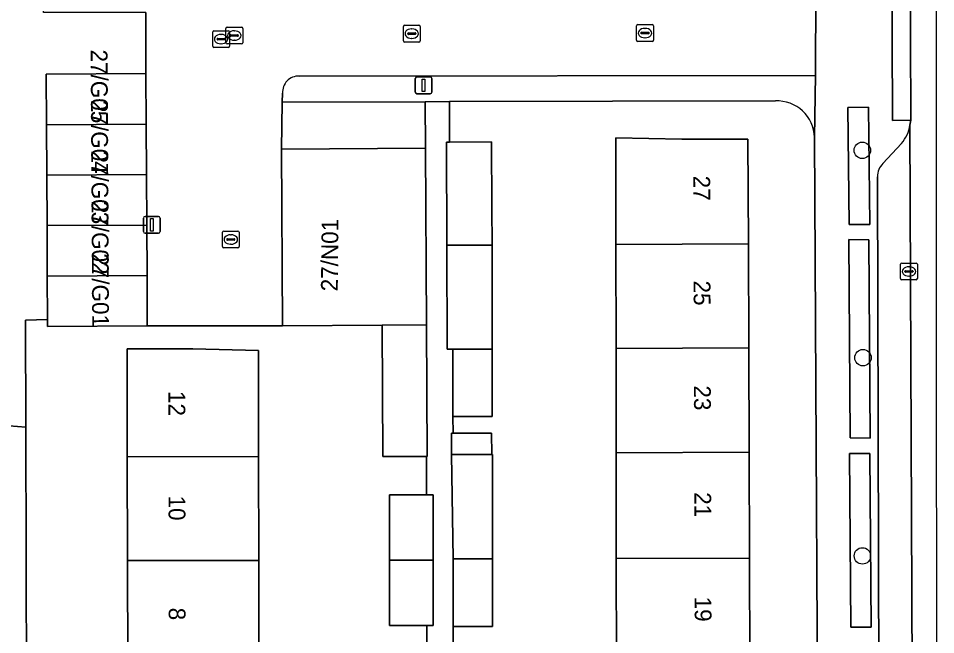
# Model space of a CAD drawing. Extents: x 160732 to 162107, y 387428 to 388479.
# Drawn here: x 161247.8 to 161302.4, y 387899 to 387935.7 of the extents above; entities that cross this region are included whole.
import ezdxf

# ---------------------------------------------------------------- set-up
doc = ezdxf.new("R2010")
doc.units = 0
for name, color, linetype in [('IMGEO_Boom', 7, 'Continuous'), ('IMGEO_Erf', 7, 'Continuous'), ('IMGEO_Groenvoorziening', 7, 'Continuous'), ('IMGEO_Haag', 7, 'Continuous'), ('IMGEO_Kolk', 7, 'Continuous'), ('IMGEO_Lichtmast', 7, 'Continuous'), ('IMGEO_Pand', 7, 'Continuous'), ('IMGEO_Pand_nummerreeks', 7, 'Continuous'), ('IMGEO_Parkeervlak_open', 7, 'Continuous'), ('IMGEO_Rijbaan_lokaal_gesloten', 7, 'Continuous'), ('IMGEO_Rijbaan_lokaal_open', 7, 'Continuous'), ('IMGEO_Rioolput', 7, 'Continuous'), ('IMGEO_Voetpad_open', 7, 'Continuous')]:
    doc.layers.add(name, color=color, linetype=linetype)

msp = doc.modelspace()

# ---------------------------------------------------------------- linework, layer by layer
at = {"layer": 'IMGEO_Boom'}
for centre in [(161298.046, 387927.814), (161298.085, 387915.474), (161298.054, 387903.682)]:
    msp.add_circle(centre, 0.489, dxfattribs=at)
at = {"layer": 'IMGEO_Erf'}
for points in [[(161292.882, 387930.752), (161273.477, 387930.71), (161273.482, 387928.303), (161275.982, 387928.317), (161276.004, 387924.389), (161276.016, 387922.172), (161276.021, 387919.765), (161276.021, 387915.984), (161276.021, 387911.974), (161273.683, 387911.974), (161273.684, 387910.985), (161275.979, 387910.992), (161275.994, 387909.712), (161276.036, 387909.712), (161276.036, 387907.273), (161276.036, 387903.515), (161276.036, 387899.482), (161273.698, 387899.482), (161273.712, 387894.91)], [(161283.411, 387897.345), (161283.404, 387903.526), (161283.396, 387909.817), (161283.389, 387916.018), (161283.382, 387922.214), (161283.375, 387928.562), (161287.301, 387928.476), (161291.227, 387928.476), (161291.281, 387922.255), (161291.3, 387916.054), (161291.32, 387909.852), (161291.34, 387903.538), (161291.359, 387897.354)], [(161295.457, 387880.84), (161295.205, 387928.599)], [(161269.924, 387891.076), (161269.919, 387894.963), (161272.127, 387894.966), (161272.122, 387899.541), (161269.91, 387899.538), (161269.905, 387903.424), (161269.9, 387907.312), (161272.113, 387907.315), (161272.11, 387909.603), (161269.512, 387909.6), (161269.469, 387917.409), (161263.537, 387917.376), (161255.49, 387917.362), (161249.554, 387917.329), (161249.552, 387917.745), (161248.248, 387917.717), (161248.263, 387911.338), (161248.335, 387880.236)], [(161250.168, 387878.512), (161254.356, 387878.531), (161254.344, 387884.882), (161254.333, 387891.056), (161254.322, 387897.231), (161254.31, 387903.406), (161254.299, 387909.58), (161254.287, 387916), (161258.196, 387916), (161262.105, 387915.903), (161262.115, 387909.59), (161262.124, 387903.415), (161262.134, 387897.241), (161262.143, 387891.066), (161262.152, 387884.891), (161262.162, 387878.605), (161269.546, 387878.658), (161269.489, 387882.632), (161272.021, 387882.669), (161272.016, 387887.191), (161269.929, 387887.189), (161269.924, 387891.076)]]:
    msp.add_lwpolyline(points, dxfattribs=at)
msp.add_arc((161292.972, 387928.519), 2.235, 2.045, 92.3052, dxfattribs=at)
at = {"layer": 'IMGEO_Groenvoorziening'}
for points in [[(161272.028, 387930.707), (161263.523, 387930.688), (161263.479, 387927.886), (161272.043, 387927.933)], [(161298.502, 387923.406), (161298.417, 387930.379), (161297.188, 387930.364), (161297.273, 387923.391)], [(161298.442, 387922.488), (161297.235, 387922.509), (161297.327, 387910.71), (161298.51, 387910.69)], [(161298.569, 387899.442), (161298.492, 387909.784), (161297.277, 387909.775), (161297.354, 387899.433)]]:
    msp.add_lwpolyline(points, close=True, dxfattribs=at)
at = {"layer": 'IMGEO_Haag'}
for points in [[(161298.502, 387923.406), (161298.417, 387930.379), (161297.188, 387930.364), (161297.273, 387923.391)], [(161298.442, 387922.488), (161297.235, 387922.509), (161297.327, 387910.71), (161298.51, 387910.69)], [(161298.569, 387899.442), (161298.492, 387909.784), (161297.277, 387909.775), (161297.354, 387899.433)]]:
    msp.add_lwpolyline(points, close=True, dxfattribs=at)
at = {"layer": 'IMGEO_Kolk'}
for p, q in [((161270.729, 387934.33), (161270.729, 387935.182)), ((161270.804, 387935.256), (161271.656, 387935.256)), ((161271.73, 387935.182), (161271.73, 387934.33)), ((161284.612, 387934.365), (161284.612, 387935.217)), ((161284.687, 387935.291), (161285.539, 387935.291)), ((161285.613, 387935.217), (161285.613, 387934.365)), ((161260.166, 387934.217), (161260.166, 387935.069)), ((161260.241, 387935.143), (161261.093, 387935.143)), ((161260.425, 387934.637), (161260.425, 387934.649)), ((161260.468, 387934.686), (161260.866, 387934.686)), ((161260.654, 387934.923), (161260.679, 387934.923)), ((161260.909, 387934.649), (161260.909, 387934.637)), ((161261.167, 387935.069), (161261.167, 387934.217)), ((161270.988, 387934.75), (161270.988, 387934.762)), ((161271.426, 387934.713), (161271.028, 387934.713)), ((161271.031, 387934.799), (161271.429, 387934.799)), ((161271.217, 387935.036), (161271.242, 387935.036)), ((161271.472, 387934.762), (161271.472, 387934.75)), ((161284.871, 387934.785), (161284.871, 387934.797)), ((161285.309, 387934.748), (161284.911, 387934.748)), ((161284.914, 387934.834), (161285.312, 387934.834)), ((161285.1, 387935.071), (161285.125, 387935.071)), ((161285.355, 387934.797), (161285.355, 387934.785)), ((161261.093, 387934.143), (161260.241, 387934.143)), ((161260.863, 387934.6), (161260.465, 387934.6)), ((161260.677, 387934.363), (161260.652, 387934.363)), ((161271.656, 387934.256), (161270.804, 387934.256)), ((161271.24, 387934.476), (161271.215, 387934.476)), ((161285.539, 387934.291), (161284.687, 387934.291)), ((161285.123, 387934.511), (161285.098, 387934.511)), ((161259.959, 387922.084), (161259.959, 387922.936)), ((161260.034, 387923.01), (161260.886, 387923.01)), ((161260.447, 387922.79), (161260.472, 387922.79)), ((161260.96, 387922.936), (161260.96, 387922.084)), ((161260.218, 387922.504), (161260.218, 387922.516)), ((161260.656, 387922.467), (161260.258, 387922.467)), ((161260.261, 387922.553), (161260.659, 387922.553)), ((161260.47, 387922.23), (161260.445, 387922.23)), ((161260.702, 387922.516), (161260.702, 387922.504)), ((161260.886, 387922.01), (161260.034, 387922.01)), ((161300.322, 387920.182), (161300.322, 387921.034)), ((161300.397, 387921.108), (161301.249, 387921.108)), ((161301.323, 387921.034), (161301.323, 387920.182)), ((161300.581, 387920.602), (161300.581, 387920.614)), ((161301.019, 387920.565), (161300.621, 387920.565)), ((161300.624, 387920.651), (161301.022, 387920.651)), ((161300.81, 387920.888), (161300.835, 387920.888)), ((161301.065, 387920.614), (161301.065, 387920.602)), ((161301.249, 387920.108), (161300.397, 387920.108)), ((161300.833, 387920.328), (161300.808, 387920.328))]:
    msp.add_line(p, q, dxfattribs=at)
for points in [[(161270.729, 387934.33), (161270.729, 387935.182)], [(161270.804, 387935.256), (161271.656, 387935.256)], [(161271.73, 387935.182), (161271.73, 387934.33)], [(161284.612, 387934.365), (161284.612, 387935.217)], [(161284.687, 387935.291), (161285.539, 387935.291)], [(161285.613, 387935.217), (161285.613, 387934.365)], [(161260.166, 387934.217), (161260.166, 387935.069)], [(161260.241, 387935.143), (161261.093, 387935.143)], [(161261.167, 387935.069), (161261.167, 387934.217)], [(161261.093, 387934.143), (161260.241, 387934.143)], [(161271.656, 387934.256), (161270.804, 387934.256)], [(161285.539, 387934.291), (161284.687, 387934.291)], [(161259.959, 387922.084), (161259.959, 387922.936)], [(161260.034, 387923.01), (161260.886, 387923.01)], [(161260.96, 387922.936), (161260.96, 387922.084)], [(161260.886, 387922.01), (161260.034, 387922.01)], [(161300.322, 387920.182), (161300.322, 387921.034)], [(161300.397, 387921.108), (161301.249, 387921.108)], [(161301.323, 387921.034), (161301.323, 387920.182)], [(161301.249, 387920.108), (161300.397, 387920.108)]]:
    msp.add_lwpolyline(points, dxfattribs=at)
for centre, radius, start, end in [((161270.806, 387935.18), 0.0765, 91.552, 178.448), ((161270.806, 387935.18), 0.0765, 91.552, 178.448), ((161271.654, 387935.18), 0.0765, 1.552, 88.448), ((161271.654, 387935.18), 0.0765, 1.552, 88.448), ((161284.689, 387935.215), 0.0765, 91.552, 178.448), ((161284.689, 387935.215), 0.0765, 91.552, 178.448), ((161285.537, 387935.215), 0.0765, 1.552, 88.448), ((161285.537, 387935.215), 0.0765, 1.552, 88.448), ((161260.243, 387935.067), 0.0765, 91.552, 178.448), ((161260.243, 387935.067), 0.0765, 91.552, 178.448), ((161260.465, 387934.646), 0.0403, 85.8775, 175.7526), ((161260.462, 387934.636), 0.0366, 178.938, 274.7102), ((161260.866, 387934.643), 0.043, 264.8664, 352.4533), ((161260.87, 387934.648), 0.0386, 1.7309, 96.639), ((161261.091, 387935.067), 0.0765, 1.552, 88.448), ((161261.091, 387935.067), 0.0765, 1.552, 88.448), ((161271.028, 387934.759), 0.0403, 85.8775, 175.7526), ((161271.025, 387934.749), 0.0366, 178.938, 274.7102), ((161271.429, 387934.756), 0.043, 264.8664, 352.4533), ((161271.433, 387934.761), 0.0386, 1.7309, 96.639), ((161284.911, 387934.794), 0.0403, 85.8775, 175.7526), ((161284.908, 387934.784), 0.0366, 178.938, 274.7102), ((161285.312, 387934.791), 0.043, 264.8664, 352.4533), ((161285.316, 387934.796), 0.0386, 1.7309, 96.639), ((161260.243, 387934.219), 0.0765, 181.552, 268.448), ((161260.243, 387934.219), 0.0765, 181.552, 268.448), ((161261.091, 387934.219), 0.0765, 271.552, 358.448), ((161261.091, 387934.219), 0.0765, 271.552, 358.448), ((161270.806, 387934.332), 0.0765, 181.552, 268.448), ((161270.806, 387934.332), 0.0765, 181.552, 268.448), ((161271.654, 387934.332), 0.0765, 271.552, 358.448), ((161271.654, 387934.332), 0.0765, 271.552, 358.448), ((161284.689, 387934.367), 0.0765, 181.552, 268.448), ((161284.689, 387934.367), 0.0765, 181.552, 268.448), ((161285.537, 387934.367), 0.0765, 271.552, 358.448), ((161285.537, 387934.367), 0.0765, 271.552, 358.448), ((161260.036, 387922.934), 0.0765, 91.552, 178.448), ((161260.036, 387922.934), 0.0765, 91.552, 178.448), ((161260.884, 387922.934), 0.0765, 1.552, 88.448), ((161260.884, 387922.934), 0.0765, 1.552, 88.448), ((161260.036, 387922.086), 0.0765, 181.552, 268.448), ((161260.036, 387922.086), 0.0765, 181.552, 268.448), ((161260.258, 387922.513), 0.0403, 85.8775, 175.7526), ((161260.255, 387922.503), 0.0366, 178.938, 274.7102), ((161260.659, 387922.51), 0.043, 264.8664, 352.4533), ((161260.663, 387922.515), 0.0386, 1.7309, 96.639), ((161260.884, 387922.086), 0.0765, 271.552, 358.448), ((161260.884, 387922.086), 0.0765, 271.552, 358.448), ((161300.399, 387921.032), 0.0765, 91.552, 178.448), ((161300.399, 387921.032), 0.0765, 91.552, 178.448), ((161301.247, 387921.032), 0.0765, 1.552, 88.448), ((161301.247, 387921.032), 0.0765, 1.552, 88.448), ((161300.621, 387920.611), 0.0403, 85.8775, 175.7526), ((161300.618, 387920.601), 0.0366, 178.938, 274.7102), ((161301.022, 387920.608), 0.043, 264.8664, 352.4533), ((161301.026, 387920.613), 0.0386, 1.7309, 96.639), ((161300.399, 387920.184), 0.0765, 181.552, 268.448), ((161300.399, 387920.184), 0.0765, 181.552, 268.448), ((161301.247, 387920.184), 0.0765, 271.552, 358.448), ((161301.247, 387920.184), 0.0765, 271.552, 358.448)]:
    msp.add_arc(centre, radius, start, end, dxfattribs=at)
for centre, major_axis, ratio, start_param, end_param in [((161260.653, 387934.643), (-0.387, 0.002), 0.722429, 4.712389, 7.853982), ((161260.678, 387934.643), (-0.39, 0.002), 0.717154, 1.570796, 4.712389), ((161271.216, 387934.756), (-0.387, 0.002), 0.722429, 4.712389, 7.853982), ((161271.241, 387934.756), (-0.39, 0.002), 0.717154, 1.570796, 4.712389), ((161285.099, 387934.791), (-0.387, 0.002), 0.722429, 4.712389, 7.853982), ((161285.124, 387934.791), (-0.39, 0.002), 0.717154, 1.570796, 4.712389), ((161260.446, 387922.51), (-0.387, 0.002), 0.722429, 4.712389, 7.853982), ((161260.471, 387922.51), (-0.39, 0.002), 0.717154, 1.570796, 4.712389), ((161300.809, 387920.608), (-0.387, 0.002), 0.722429, 4.712389, 7.853982), ((161300.834, 387920.608), (-0.39, 0.002), 0.717154, 1.570796, 4.712389)]:
    msp.add_ellipse(centre, major_axis=major_axis, ratio=ratio, start_param=start_param, end_param=end_param, dxfattribs=at)
at = {"layer": 'IMGEO_Lichtmast'}
for p, q in [((161271.437, 387931.279), (161271.437, 387932.079)), ((161271.437, 387932.079), (161271.437, 387931.279)), ((161271.537, 387932.179), (161272.327, 387932.179)), ((161272.327, 387932.179), (161271.537, 387932.179)), ((161272.427, 387932.079), (161272.427, 387931.279)), ((161272.427, 387931.279), (161272.427, 387932.079)), ((161272.327, 387931.179), (161271.537, 387931.179)), ((161271.537, 387931.179), (161272.327, 387931.179)), ((161255.262, 387922.979), (161255.262, 387923.779)), ((161255.262, 387923.779), (161255.262, 387922.979)), ((161255.362, 387923.879), (161256.152, 387923.879)), ((161256.152, 387923.879), (161255.362, 387923.879)), ((161256.252, 387923.779), (161256.252, 387922.979)), ((161256.252, 387922.979), (161256.252, 387923.779)), ((161256.152, 387922.879), (161255.362, 387922.879)), ((161255.362, 387922.879), (161256.152, 387922.879))]:
    msp.add_line(p, q, dxfattribs=at)
for points in [[(161271.857, 387932.054), (161272.007, 387932.054), (161272.007, 387931.304), (161271.857, 387931.304), (161271.857, 387932.054)], [(161255.682, 387923.754), (161255.832, 387923.754), (161255.832, 387923.004), (161255.682, 387923.004), (161255.682, 387923.754)]]:
    msp.add_lwpolyline(points, dxfattribs=at)
for centre, start, end in [((161271.537, 387932.079), 90, 180), ((161271.537, 387932.079), 90, 180), ((161272.327, 387932.079), 0, 90), ((161272.327, 387932.079), 360, 90), ((161271.537, 387931.279), 180, 270), ((161271.537, 387931.279), 180, 270), ((161272.327, 387931.279), 270, 0), ((161272.327, 387931.279), 270, 0), ((161255.362, 387923.779), 90, 180), ((161255.362, 387923.779), 90, 180), ((161256.152, 387923.779), 0, 90), ((161256.152, 387923.779), 360, 90), ((161255.362, 387922.979), 180, 270), ((161255.362, 387922.979), 180, 270), ((161256.152, 387922.979), 270, 0), ((161256.152, 387922.979), 270, 0)]:
    msp.add_arc(centre, 0.1, start, end, dxfattribs=at)
at = {"layer": 'IMGEO_Pand'}
for points in [[(161255.406, 387932.376), (161249.47, 387932.343), (161249.487, 387929.34), (161255.423, 387929.373)], [(161255.423, 387929.373), (161249.487, 387929.34), (161249.504, 387926.337), (161255.44, 387926.37)], [(161273.482, 387928.303), (161273.288, 387928.302), (161273.313, 387922.164), (161273.516, 387922.164), (161273.683, 387922.165), (161276.016, 387922.172), (161276.004, 387924.389), (161275.982, 387928.317)], [(161283.375, 387928.562), (161283.382, 387922.214), (161291.281, 387922.255), (161291.227, 387928.476), (161287.301, 387928.476)], [(161272.043, 387927.933), (161263.479, 387927.886), (161263.537, 387917.376), (161269.469, 387917.409), (161272.101, 387917.423)], [(161255.44, 387926.37), (161249.504, 387926.337), (161249.52, 387923.334), (161255.456, 387923.368)], [(161255.456, 387923.368), (161249.52, 387923.334), (161249.537, 387920.332), (161255.473, 387920.365)], [(161276.021, 387919.765), (161276.016, 387922.172), (161273.683, 387922.165), (161273.516, 387922.164), (161273.313, 387922.164), (161273.339, 387915.973), (161273.551, 387915.973), (161273.683, 387915.974), (161276.021, 387915.984)], [(161283.382, 387922.214), (161283.389, 387916.018), (161291.3, 387916.054), (161291.281, 387922.255)], [(161255.473, 387920.365), (161249.537, 387920.332), (161249.552, 387917.745), (161249.554, 387917.329), (161255.49, 387917.362)], [(161272.101, 387917.423), (161269.469, 387917.409), (161269.512, 387909.6), (161272.11, 387909.603), (161272.144, 387909.603)], [(161291.32, 387909.852), (161291.3, 387916.054), (161283.389, 387916.018), (161283.396, 387909.817)], [(161254.287, 387916), (161254.299, 387909.58), (161262.115, 387909.59), (161262.105, 387915.903), (161258.196, 387916)], [(161273.683, 387911.974), (161276.021, 387911.974), (161276.021, 387915.984), (161273.683, 387915.974)], [(161275.979, 387910.992), (161273.684, 387910.985), (161273.586, 387910.985), (161273.586, 387909.713), (161273.698, 387909.713), (161275.994, 387909.712)], [(161254.31, 387903.406), (161262.124, 387903.415), (161262.115, 387909.59), (161254.299, 387909.58)], [(161276.036, 387907.273), (161276.036, 387909.712), (161275.994, 387909.712), (161273.698, 387909.713), (161273.586, 387909.713), (161273.698, 387903.511), (161276.036, 387903.515)], [(161291.34, 387903.538), (161291.32, 387909.852), (161283.396, 387909.817), (161283.404, 387903.526)], [(161272.495, 387907.315), (161272.113, 387907.315), (161269.9, 387907.312), (161269.905, 387903.424), (161272.5, 387903.427)], [(161273.698, 387899.482), (161276.036, 387899.482), (161276.036, 387903.515), (161273.698, 387903.511)], [(161283.404, 387903.526), (161283.411, 387897.345), (161291.359, 387897.354), (161291.34, 387903.538)], [(161254.322, 387897.231), (161262.134, 387897.241), (161262.124, 387903.415), (161254.31, 387903.406)], [(161272.5, 387903.427), (161269.905, 387903.424), (161269.91, 387899.538), (161272.122, 387899.541), (161272.505, 387899.541)]]:
    msp.add_lwpolyline(points, close=True, dxfattribs=at)
at = {"layer": 'IMGEO_Parkeervlak_open'}
for points in [[(161301.088, 387878.113), (161300.884, 387929.313)], [(161300.386, 387928.226), (161299.273, 387927.025)], [(161298.953, 387926.242), (161299.074, 387881.148)]]:
    msp.add_lwpolyline(points, dxfattribs=at)
for centre, radius, start, end in [((161298.672, 387929.669), 2.241, 319.9102, 350.8608), ((161300.007, 387926.268), 1.054, 134.1128, 181.429)]:
    msp.add_arc(centre, radius, start, end, dxfattribs=at)
at = {"layer": 'IMGEO_Rijbaan_lokaal_gesloten'}
msp.add_lwpolyline([(161300.888, 387939.893), (161300.899, 387939.625), (161300.931, 387929.617), (161300.884, 387929.313), (161301.088, 387878.113), (161301.089, 387875.8), (161302.479, 387875.8), (161302.479, 387897.971), (161302.464, 387915.139), (161302.464, 387992.392), (161300.785, 387992.369), (161300.83, 387991.744), (161300.779, 387991.22)], close=True, dxfattribs=at)
at = {"layer": 'IMGEO_Rijbaan_lokaal_open'}
for points in [[(161264.524, 387932.232), (161295.254, 387932.26), (161295.274, 387937.307), (161271.508, 387937.226)], [(161255.398, 387936.01), (161255.406, 387932.376), (161255.423, 387929.373), (161255.44, 387926.37), (161255.456, 387923.368), (161255.473, 387920.365), (161255.49, 387917.362), (161263.537, 387917.376), (161263.479, 387927.886), (161263.523, 387930.688), (161263.54, 387931.219)]]:
    msp.add_lwpolyline(points, dxfattribs=at)
msp.add_arc((161264.496, 387931.275), 0.958, 88.3174, 183.3465, dxfattribs=at)
at = {"layer": 'IMGEO_Rioolput'}
for p, q in [((161259.38, 387934.006), (161259.38, 387934.858)), ((161259.455, 387934.932), (161260.307, 387934.932)), ((161259.868, 387934.712), (161259.893, 387934.712)), ((161260.381, 387934.858), (161260.381, 387934.006)), ((161259.639, 387934.426), (161259.639, 387934.438)), ((161260.077, 387934.389), (161259.679, 387934.389)), ((161259.682, 387934.475), (161260.08, 387934.475)), ((161259.891, 387934.152), (161259.866, 387934.152)), ((161260.123, 387934.438), (161260.123, 387934.426)), ((161260.307, 387933.932), (161259.455, 387933.932))]:
    msp.add_line(p, q, dxfattribs=at)
for points in [[(161259.38, 387934.006), (161259.38, 387934.858)], [(161259.455, 387934.932), (161260.307, 387934.932)], [(161260.381, 387934.858), (161260.381, 387934.006)], [(161260.307, 387933.932), (161259.455, 387933.932)]]:
    msp.add_lwpolyline(points, dxfattribs=at)
for centre, radius, start, end in [((161259.457, 387934.856), 0.0765, 91.552, 178.448), ((161259.457, 387934.856), 0.0765, 91.552, 178.448), ((161260.305, 387934.856), 0.0765, 1.552, 88.448), ((161260.305, 387934.856), 0.0765, 1.552, 88.448), ((161259.679, 387934.435), 0.0403, 85.8775, 175.7526), ((161259.676, 387934.425), 0.0366, 178.938, 274.7102), ((161260.08, 387934.432), 0.043, 264.8664, 352.4533), ((161260.084, 387934.437), 0.0386, 1.7309, 96.639), ((161259.457, 387934.008), 0.0765, 181.552, 268.448), ((161259.457, 387934.008), 0.0765, 181.552, 268.448), ((161260.305, 387934.008), 0.0765, 271.552, 358.448), ((161260.305, 387934.008), 0.0765, 271.552, 358.448)]:
    msp.add_arc(centre, radius, start, end, dxfattribs=at)
for centre, major_axis, ratio, start_param, end_param in [((161259.867, 387934.432), (-0.387, 0.002), 0.722429, 4.712389, 7.853982), ((161259.892, 387934.432), (-0.39, 0.002), 0.717154, 1.570796, 4.712389)]:
    msp.add_ellipse(centre, major_axis=major_axis, ratio=ratio, start_param=start_param, end_param=end_param, dxfattribs=at)
at = {"layer": 'IMGEO_Voetpad_open'}
for points in [[(161295.299, 387997.485), (161295.151, 387986.728), (161295.265, 387940.831), (161295.274, 387937.307), (161295.254, 387932.26), (161295.205, 387928.599), (161295.457, 387880.84)], [(161249.47, 387932.343), (161255.406, 387932.376), (161255.398, 387936.01), (161249.318, 387936.014), (161249.32, 387938.233), (161249.32, 387938.83), (161249.322, 387941.849), (161249.324, 387944.869), (161249.326, 387947.888), (161249.328, 387950.908), (161248.138, 387950.901), (161248.135, 387952.571), (161243.083, 387952.638)], [(161245.206, 387950.779), (161245.221, 387939.638), (161245.226, 387936.499), (161245.231, 387932.734), (161245.233, 387931.329), (161245.26, 387911.586), (161248.263, 387911.338), (161248.248, 387917.717), (161249.552, 387917.745), (161249.537, 387920.332), (161249.52, 387923.334), (161249.504, 387926.337), (161249.487, 387929.34), (161249.47, 387932.343)], [(161300.884, 387929.313), (161300.931, 387929.617), (161299.842, 387929.595), (161299.808, 387939.642), (161300.899, 387939.625), (161300.888, 387939.893)], [(161295.254, 387932.26), (161264.524, 387932.232)], [(161295.205, 387928.599), (161295.254, 387932.26)], [(161263.54, 387931.219), (161263.523, 387930.688), (161272.028, 387930.707), (161273.477, 387930.71), (161292.882, 387930.752)], [(161273.712, 387894.91), (161273.698, 387899.482), (161273.698, 387903.511), (161273.586, 387909.713), (161273.586, 387910.985), (161273.684, 387910.985), (161273.683, 387911.974), (161273.683, 387915.974), (161273.551, 387915.973), (161273.339, 387915.973), (161273.313, 387922.164), (161273.288, 387928.302), (161273.482, 387928.303), (161273.477, 387930.71), (161272.028, 387930.707), (161272.043, 387927.933), (161272.101, 387917.423), (161272.144, 387909.603), (161272.11, 387909.603), (161272.113, 387907.315), (161272.495, 387907.315), (161272.5, 387903.427), (161272.505, 387899.541), (161272.122, 387899.541), (161272.127, 387894.966)], [(161299.273, 387927.025), (161300.386, 387928.226)], [(161299.074, 387881.148), (161298.953, 387926.242)]]:
    msp.add_lwpolyline(points, dxfattribs=at)
for points in [[(161300.899, 387939.625), (161299.808, 387939.642), (161299.842, 387929.595), (161300.931, 387929.617)], [(161298.417, 387930.379), (161298.502, 387923.406), (161297.273, 387923.391), (161297.188, 387930.364)], [(161298.442, 387922.488), (161298.51, 387910.69), (161297.327, 387910.71), (161297.235, 387922.509)], [(161248.506, 387875.48), (161248.329, 387880.157), (161248.335, 387880.236), (161248.263, 387911.338), (161245.26, 387911.586), (161217.792, 387911.526), (161217.608, 387909.867), (161217.608, 387907.852), (161217.603, 387897.233), (161217.776, 387892.744), (161217.778, 387860.958), (161222.59, 387860.981), (161248.537, 387861.034), (161248.537, 387862.996), (161248.554, 387864.996)], [(161298.492, 387909.784), (161298.569, 387899.442), (161297.354, 387899.433), (161297.277, 387909.775)]]:
    msp.add_lwpolyline(points, close=True, dxfattribs=at)
for centre, radius, start, end in [((161264.496, 387931.275), 0.958, 88.3174, 183.3465), ((161292.972, 387928.519), 2.235, 2.045, 92.3052), ((161298.672, 387929.669), 2.241, 319.9102, 350.8608), ((161300.007, 387926.268), 1.054, 134.1128, 181.429)]:
    msp.add_arc(centre, radius, start, end, dxfattribs=at)

# ---------------------------------------------------------------- texts
at = {"layer": 'IMGEO_Pand_nummerreeks'}
for s, rotation, p in [('27/G05', 270.3206, (161252.118, 387933.807)), ('27/G04', 270.3206, (161252.135, 387930.804)), ('27/G03', 270.3206, (161252.152, 387927.801)), ('27', 270.1802, (161287.988, 387926.303)), ('27/G02', 270.3206, (161252.168, 387924.805)), ('27/N01', 89.4215, (161266.824, 387919.421)), ('27/G01', 270.3206, (161252.186, 387921.685)), ('25', 270.1802, (161288.007, 387920.064)), ('12', 270.0692, (161256.747, 387913.494)), ('23', 270.1802, (161288.027, 387913.825)), ('21', 270.1802, (161288.048, 387907.473)), ('10', 270.0692, (161256.754, 387907.274)), ('19', 270.1802, (161288.067, 387901.257)), ('8', 270.0692, (161256.763, 387900.6))]:
    msp.add_text(s, height=1, rotation=rotation, dxfattribs=at).set_placement(p)

doc.saveas('drawing.dxf')
